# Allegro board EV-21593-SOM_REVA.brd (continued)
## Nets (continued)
PC_01/LP1_D2/TWI4_SDA/TRACE0_D05/SPI2_SEL4B: J2.92 U1.W15
PC_02/LP1_D3/TWI5_SCL/TRACE0_D06/SPI1_SEL6B: J2.90 U1.Y15
PC_03/LP1_D4/TWI5_SDA/TRACE0_D07/SPI2_SEL6B: J2.88 U1.W16
PC_04/LP1_D5/OSPI_SEL2B/SMC0_ADDR5: J2.86 U1.Y17
PC_05/LP1_D6/OSPI_SEL3B/TM0_TMR8/SMC0_ADDR6: J2.84 U1.V14
PC_06/LP1_D7/SPI1_RDY/SMC0_ADDR7: J2.82 U1.W17
PC_07/LP1_CLK/OSPI_SEL4B/TM0_TMR9/SYS_FAULT: J2.100 U1.Y18
PG1: R56.2 U14.2 U15.1
PG3: R62.1 U5.1 U14.11
PG4: R61.1 U5.14
RXD: U10.2 U11.8
SPIFLASH_SPI2D2: R79.2 U2.9 U7.4
SPIFLASH_SPI2D3: R78.2 U2.1 U8.4
SYS_BMODE0: R20.1 SW1.1 U1.B10
SYS_BMODE1: R21.1 SW1.2 U1.B9
SYS_BMODE2: R22.1 SW1.4 U1.A8
SYS_CLKIN0: R23.2 R33.2 U1.N1
SYS_CLKOUT: J3.38 U1.M3
SYS_XTAL0: R32.1 U1.L1
TWI2_SCL: J2.39 R68.2 R70.2 R112.2 U9.12 U16.8
TWI2_SDA: J2.41 R67.2 R69.2 R113.2 U9.19 U16.9
TXD: U10.30 U11.11
USB_SHELL: C192.1 P2.6 P2.7 P2.8 P2.9 R82.1
USB_VBUS: C191.1 D1.1 FER1.1 P2.1
VTT: C1.1 C2.1 C3.1 C4.1 C17.1 C18.1 C19.1 C20.1 C34.1 C35.1 C201.1 C202.1 C203.1 C204.1 C205.1 C206.1 C207.1 RN1.5 RN1.6 RN1.7 RN1.8 RN2.5 RN2.6 RN2.7 RN2.8 RN3.5 RN3.6 RN3.7 RN3.8 RN4.5 RN4.6 RN4.7 RN4.8 RN5.5 RN5.6 RN5.7 RN5.8 RN6.5 RN6.6 RN6.7 RN6.8 RN7.7 RN7.8 U12.3 U12.5
~CON_RESET_IN: J3.96 R51.2 U18.2
~CTS: R86.2 U10.8 U11.3
~DMC0_CAS: RN6.3 U1.E20 U13.K3
~DMC0_CK: R16.2 U1.J19 U13.K7
~DMC0_CS0: RN6.4 U1.F20 U13.L2
~DMC0_LDQS: U1.F1 U13.G3
~DMC0_RAS: RN6.1 U1.F19 U13.J3
~DMC0_RESET: R6.2 RN2.1 U1.B12 U13.T2
~DMC0_UDQS: U1.A4 U13.B7
~DMC0_WE: RN1.3 U1.A12 U13.L3
~JTG0_TRST: J3.56 P1.9 R92.2 R93.1 U1.A10
~RTS: R87.2 U10.32 U11.6
~SP2IFLASH_CS_EN: R75.2 R81.1 U6.1 U16.20
~SPI2D2_D3_EN: R74.1 R76.2 U7.1 U8.1 U16.21
~SPIFLASH_CS: R77.2 U2.7 U6.4
~SYS_FAULT: R9.2 R10.2 U1.A11
~SYS_HWRST: J3.94 R12.1 R46.2 R48.2 U1.A9 U2.3 U4.2 U16.14
~SYS_RESOUT: R11.2 U1.C10
~TARGET_RESET: J3.58 R50.2 R94.2 U18.1
~UART0_EN: R88.1 U11.10 U11.13 U16.22
~UART0_FLOW_EN: R89.1 U11.1 U11.4 U16.23
$3N3239: R2.2 U1.G20 U1.J4
$3N3333: R5.1 U13.L8
$3N3334: C11.2 C12.1 C13.1 C14.1 C15.1 C16.1 R3.2 R4.1 R7.1 U13.H1 U13.M8
$3N6009: C7.1 R100.2 R101.1 U12.1
$3N6012: R8.1 U12.6
$4N2087: LED1.K R9.1
$5N38: R71.1 R73.2 U2.16
$5N56: R72.1 R80.2 U2.8
$6N1711: C28.1 C29.1 FER3.3 U1.L20
$6N2071: R13.1 U1.L18
$6N3598: C30.1 C31.1 FER4.3 U1.L19
$6N4036: FER4.1 R14.2
$6N5154: C33.2 R15.1
$6N5877: R119.2 R120.2 U1.L7 U1.M7
$8N2576: C145.1 R25.2 U9.7 U9.24
$8N2596: R23.1 U9.22
$8N2617: R18.1 R19.2 U9.5
$8N2622: U9.1 Y2.2
$8N2623: U9.2 Y2.1
$8N2657: R24.1 U9.14
$8N3809: C144.1 R27.2 U9.16 U9.20
$8N3812: C143.1 R28.2 U9.11 U9.15
$8N3997: R30.1 U9.18
$8N3999: R31.1 U9.10
$8N4014: R32.2 R34.1 R35.1
$8N4015: C142.1 R33.1 R34.2 Y1.2
$8N4293: C141.1 R35.2 Y1.1
$9N2124: FER2.1 P2.5
$9N2147: LED7.K R83.1
$9N2148: LED8.K R84.1
$9N2149: R84.2 U10.22
$9N2150: R83.2 U10.21
$9N2153: D2.1 P2.2 U10.15
$9N2154: D2.2 P2.3 U10.14
$9N2155: C193.1 C194.1 FER1.2 U10.19
$9N2158: R85.2 U10.18
$9N3466: P1.10 R94.1
$10N4563: J3.95 R99.2
$10N4564: J3.93 R98.2
$10N4565: J3.91 R97.2
$10N4566: J3.89 R96.2
$10N4567: J3.87 R95.2
$11N466: R47.2 U4.3 U17.4
$11N467: LED6.K R46.1
$11N468: R49.2 SW2.2 U17.2
$11N469: U17.1 U18.4
$11N1122: LED4.K R38.1
$11N1123: LED5.K R37.1
$11N1124: LED3.K R39.1
$11N1132: LED2.K R36.1
$11N1711: LED2.A U16.19
$11N1713: LED5.A U16.18
$11N1715: LED4.A U16.17
$11N2516: R41.1 R42.2 U16.12
$11N2517: R44.1 R45.2 U16.13
$11N2518: R40.2 R43.1 U16.11
$12N6006: C163.2 R54.1 R55.2 U15.19 U15.20
$12N6225: L3.1 U14.5 U14.6
$12N6230: C151.2 R52.1 R63.2 U14.12
$12N7569: C162.2 L4.1 U15.8 U15.9 U15.10
$12N7589: C162.1 U15.7
$12N7788: R57.2 R58.2 R121.1 U15.15
$12N7803: C168.1 R121.2 R122.1 R123.1 R124.2 U15.18
$12N7837: R59.1 U15.17
$12N8016: C173.2 U5.16
$12N8049: C174.1 R60.2
$12N8051: C174.2 C185.2 R65.1 U5.17
$12N8198: L5.1 U5.6 U5.7 U5.8 U5.9
$12N8425: R66.2 R117.1
$12N8479: C178.2 C218.1 R64.2 R65.2 R66.1 R116.1 U5.18
$12N8484: R52.2 R118.1
$12N8942: R29.2 R127.2 U15.14
$13N133: C208.1 D4.A D5.K P3.A4 P3.A9 P3.B4 P3.B9 R110.1 U19.5 U19.6 U19.7 U19.8 U19.9
$13N256: R17.2 R103.1 U21.13
$13N259: R102.2 R104.1 U21.12
$13N306: R105.1 R115.1 U21.6
$13N308: R112.1 U21.7
$13N309: R113.1 U21.8
$13N457: R106.2 R107.1 R108.1 U19.4 U20.4
$13N525: C212.2 R108.2
$13N528: R107.2 U21.16
$13N538: R114.1 U21.19
$13N593: C213.1 D4.K R109.1 R110.2
$13N599: R109.2 U21.18
$13N626: R111.2 U21.9

Pads without a net: D1 3 4 6; D2 4 5 6 7 9 10; D3 4 5; J1 27 28 29 30 31 32 33 34 35 36 37 38 48 50 52 54 57 58 59 60 61 62 63 64 65 66 67 68 69 70 71 72 73 74 75 76 77 78 79 80 81 82 83 84 85 86 89 91 93 95 97 99; J2 29 53 54 55 56 57 58 59 60 61 63 64 65 66 67 69 70 72 73 74 75 77; J3 3 4 5 6 7 8 9 10 11 12 13 14 15 16 17 18 19 20 21 23 24 26 27 28 29 30 31 32 33 34 35 37 43 45 47 49 51 53 55 57 59 61 62 63 64 65 66 67 68 69 70 71 72 73 74 75 77 78 79 80 81 82 83 84 86 88; P1 7; P2 4 10 11; P3 A2 A3 A6 A7 A8 A10 A11 B2 B3 B6 B7 B8 B10 B11 S3 S4; RN7 3 4 5 6; SW1 8 C1; SW2 3 4 5; U2 4 5 6 11 12 13 14; U3 4; U9 8 9 13 17 21; U10 3 5 6 7 9 10 11 12 13 23 25 27 28 29 31; U12 9; U13 J1 J9 L1 L9; U15 5 12 16 22 23 24 25; U16 1 2 3 4 7 10 15 16 24 25 26 27 28; U21 11 14 15 17 20 V1 V2 V3 V4 V5; ZF1 1; ZF2 1; ZF3 1; ZF4 1; ZF5 1; ZF6 1

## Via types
v1: diameter 0.445, hole 0.152, TOP to BOTTOM, 2159 vias
v2: diameter 0.635, hole 0.305, TOP to BOTTOM, 1154 vias
v3: diameter 0.635, hole 0.302, TOP to BOTTOM, 121 vias

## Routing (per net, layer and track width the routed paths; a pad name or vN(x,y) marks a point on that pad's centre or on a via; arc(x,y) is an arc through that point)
1V2: length 2.1
  TOP w0.254: v2(46.35,96.65) 46.6,96.27 U21.21
  BOTTOM w0.508: C210.2 v2(46.35,96.65)
2V7: length 18.1
  TOP w0.254: v2(45.47,96.65) 45.6,96.27 U21.23
  TOP w0.305: R17.1 R102.1 v2(47.62,88.9)
  L5_SIG w0.305: v2(47.62,88.9) 47.62,89.66 47.12,90.17 45.59,90.17 45.02,90.74 43.37,90.74 42.8,91.31 42.8,96.14 43.31,96.65 v2(45.47,96.65)
  BOTTOM w0.508: C209.2 v2(45.47,96.65)
3V: length 108.9
  TOP w0.254: v2(52.44,72.19) 52.44,72.49 U12.7 ; v2(52.44,71.39) 52.44,70.99 U12.10
  TOP w0.305: R92.1 v2(10.79,47.62) ; U22.4 55.12,7.21 55.12,6.22 54.86,5.97 R125.1 ; U22.4 55.08,7.37 55.34,7.37 55.75,7.77 C219.1 56.64,7.77 ; U22.4 53.98,7.31 53.72,7.56 53.72,9.53 54.1,9.91 54.1,10.44 R126.1 54.2,11.18 53.69,11.68 53.69,12.45 54.2,12.95 54.2,20.47 v2(53.59,21.08) v2(53.59,21.84) ; TP3.1 v2(11.68,26.42) ; TP3.1 v2(11.68,28.19) ; TP3.1 v2(9.91,26.42) ; TP3.1 R53.2 ; TP3.1 v2(9.91,28.19) ; R45.1 12.32,71.25 v2(13.33,71.25) 14.22,71.25 R42.1 ; v2(5.71,80.9) SW1.C ; v2(18.92,63.37) 18.54,63.26 U16.5 ; U8.5 18.08,39.38 v2(18.1,39.37) ; v2(15.24,71.25) 16.13,71.25 R40.1 ; v1(58.8,28.07) 58.8,27.3 C149.1 58.93,27.3 59.56,26.67 59.56,25.71 U4.4 ; R47.1 R48.1 55.15,21.11 v1(55.12,21.08) ; v1(58.8,33.27) 58.8,32.38 C147.1 58.9,31.18 59.28,30.79 U17.5 ; v2(18.1,31.75) 18.08,31.76 U6.5 ; U11.14 17.27,79.04 v2(16.89,78.74) ; v1(20.62,66.34) R10.1 ; v2(22.23,37.46) 22.23,38.48 21.97,38.73 U2.2 ; R11.1 21.34,63.62 21.22,63.74 v1(20.62,63.74) ; v1(19.94,69.85) LED1.A ; v2(18.1,35.56) 18.08,35.57 U7.5 ; R49.1 54.23,29.84 v2(54.23,30.73) 54.23,31.75 LED6.A ; R50.1 v2(53.09,39.37) ; v1(59.05,42.16) 58.9,41.78 C148.1 59.44,40.74 59.44,39.68 U18.5 ; v2(6.35,99.57) LED7.A ; v2(4.45,99.57) LED8.A ; R51.1 v2(53.09,38.1) ; v2(8.26,58.42) LED3.A
  TOP w0.406: C8.1 v2(52.44,69.79)
  L2_PWR w0.406: 10.15,27.95 10.26,27.84 ; 10.15,26.66 10.26,26.77 ; 11.44,26.66 11.33,26.77 ; 11.44,27.95 11.33,27.84
  BOTTOM w0.254: C189.1 17.15,31.75 v2(18.1,31.75) ; v2(18.1,39.37) 17.15,39.37 C188.1 ; v2(18.1,35.56) 17.15,35.56 C187.1
  BOTTOM w0.305: 35.42,39.34 R67.1 ; 35.42,39.34 33.82,39.34 R68.1 ; 35.42,39.34 v1(36.22,39.34) ; R91.1 18.57,76.96 v2(20.19,76.96) ; v2(24.77,34.8) 23.59,34.8 R77.1 ; v2(10.79,33.66) R76.1 ; R87.1 v2(12.19,74.3) ; R19.1 43.18,32 v2(42.16,32) ; C186.1 v2(22.23,37.46) ; R90.1 v2(14.73,73.91) ; v2(18.92,63.37) C146.1 ; R25.1 v2(43.18,39.37) ; v2(26.03,33.02) R79.1 ; R75.1 v2(12.7,29.84) ; v2(16.89,78.74) 16,78.74 C190.1 ; R86.1 v2(12.19,79.88) ; v2(24.77,33.02) R80.1 ; R28.1 v2(48.89,31.12) ; R78.1 v2(23.49,37.46)
  BOTTOM w0.508: P1.1 3.81,56.9 4.32,57.4 7.87,57.4 8.26,57.79 v2(8.26,58.42) 8.26,60.07 7.62,60.71 v2(1.4,60.71)
  vias: v2(52.44,70.59) v2(52.44,70.59)
3V3OUT_FT232RQ: length 22.3
  TOP w0.254: U10.16 14.12,89.03 v2(13.08,89.03) ; U10.1 19.43,84.61 v2(19.81,84.33)
  TOP w0.762: v2(19.81,84.33) 20.57,84.33 20.83,84.58 20.83,90.3 20.45,90.68 13.46,90.68 13.08,90.3 v2(13.08,89.03)
  BOTTOM w0.305: v2(13.08,89.03) R85.1 ; v2(19.81,84.33) C195.1 C196.1
GND: length 516.4
  TOP w0.203: U1.L12 v1(33.82,53.34) ; U1.J13 v1(34.62,54.94) U1.H13 ; U1.D4 v1(27.42,58.94) ; U1.V16 v1(37.82,46.94) ; U13.J2 v1(33.02,73.54) ; U1.W1 v1(25.02,46.14) ; U1.T1 v1(25.02,48.54) ; U1.C5 v1(28.22,59.74) ; U1.J8 v1(31.42,54.94) ; U1.R17 v1(38.62,49.34) ; U1.V18 v1(39.42,46.94) ; U1.J9 v1(32.22,54.94) ; U1.D14 v1(36.22,58.94) ; U1.L2 v1(25.82,52.54) ; U1.Y20 v1(40.22,45.34) U1.Y19 ; U1.U17 v1(38.62,47.74) ; U1.M9 v1(32.22,52.54) ; U1.J3 v1(26.62,54.94) ; U1.Y5 v1(28.22,45.34) ; U1.K17 v1(38.62,54.14) ; U1.U5 v1(28.22,47.74) ; U1.V3 v1(26.62,46.94) ; U1.C3 v1(26.62,59.74) ; U1.H8 v1(31.42,55.74) ; U13.G1 v1(31.42,72.74) ; U1.L10 v1(32.22,53.34) ; U1.K19 v1(40.22,54.14) ; U1.K9 v1(31.42,54.14) U1.K8 ; U1.N13 v1(34.62,51.74) U1.M12 ; U1.D18 v1(39.42,58.94) ; U13.J8 v1(33.02,79.14) ; U1.D16 v1(37.82,58.94) U1.D17 ; U1.M8 v1(31.42,52.54) ; U1.U16 v1(37.82,47.74) ; U1.K20 v1(41.02,54.14) ; U1.H11 v1(33.02,54.94) U1.H10 ; U1.L9 v1(31.42,53.34) U1.L8 ; U1.J12 v1(33.82,54.94) U1.H12 ; U1.W2 v1(25.82,46.14) ; U1.A20 v1(41.02,61.34) ; U1.Y2 v1(25.82,45.34) ; U1.L3 v1(26.62,52.54) ; U13.B3 v1(27.42,74.34) ; U1.M10 v1(33.02,52.54) ; U1.B19 v1(40.22,60.54) ; U1.C6 v1(29.02,59.74) ; U13.B1 v1(27.42,72.74) ; U1.M11 v1(33.02,51.74) U1.N11 ; U1.G3 v1(26.62,56.54) ; U1.C17 v1(38.62,59.74) ; U1.D7 v1(29.82,58.94) ; U13.T9 v1(38.62,79.94) ; U13.M1 v1(35.42,72.74) ; U13.F9 v1(30.62,79.94) ; U1.M1 v1(25.82,51.74) U1.M2 ; U1.N17 v1(38.62,51.74) U1.M17 ; U1.J18 v1(39.42,54.94) ; U1.V4 v1(27.42,46.94) ; U1.K11 v1(33.82,54.14) ; U13.G9 v1(31.42,79.94) ; U13.M9 v1(35.42,79.94) ; U1.D15 v1(37.02,58.94) ; U1.K1 v1(25.82,54.14) U1.K2 ; U1.D2 v1(25.82,58.94) ; U1.C4 v1(27.42,59.74) ; U1.R2 v1(25.82,49.34) ; U1.N18 v1(39.42,51.74) U1.M18 ; U1.P1 v1(25.02,50.14) ; U1.D5 v1(28.22,58.94) ; U1.N12 v1(33.82,51.74) ; U1.N9 v1(31.42,51.74) ; U1.F3 v1(26.62,57.34) ; U1.K13 v1(34.62,54.14) U1.K12 ; U1.D13 v1(35.42,58.94) ; U1.L17 v1(38.62,52.54) ; U1.H9 v1(32.22,55.74) ; U1.E3 v1(26.62,58.14) ; U13.B9 v1(27.42,79.94) ; U13.D8 v1(29.02,79.14) ; U1.C14 v1(36.22,59.74) ; U13.D1 v1(29.02,72.74) ; U1.P20 v1(41.02,50.14) ; U1.Y13 v1(35.42,45.34) ; U1.K18 v1(39.42,54.14) ; U1.K3 v1(26.62,54.14) ; v1(38.62,50.14) U1.P17 ; U13.E2 v1(29.82,73.54) ; U1.H2 v1(25.82,55.74) ; v1(40.22,50.14) U1.P19 ; U1.T4 v1(28.22,48.54) ; U1.N10 v1(32.22,51.74) ; U1.Y16 v1(37.82,45.34) ; U1.H18 v1(39.42,55.74) U1.G18 ; U13.E1 v1(29.82,72.74) ; U1.C15 v1(37.02,59.74) ; U13.P9 v1(37.02,79.94) ; U1.L11 v1(33.82,52.54) ; U13.T1 v1(38.62,72.74) ; U1.C16 v1(37.82,59.74) ; U1.U1 v1(25.02,47.74) ; U13.G8 v1(31.42,79.14) ; U1.Y1 v1(25.02,45.34) ; U1.U4 v1(27.42,47.74) ; U1.N2 v1(25.82,50.94) ; U1.V15 v1(37.02,46.94) ; U1.C18 v1(39.42,59.74) ; U1.B1 v1(25.02,60.54) ; U1.A1 v1(25.02,61.34) ; U1.J10 v1(32.22,54.14) ; U1.B2 v1(25.82,60.54) ; U1.F18 v1(39.42,56.54) ; U1.D6 v1(29.02,58.94) ; U1.H3 v1(26.62,55.74) ; U1.W20 v1(40.22,46.14) U1.W19 ; U13.A9 v1(26.62,79.94) ; U1.N8 v1(30.62,51.74) ; U13.P1 v1(37.02,72.74) ; U1.D12 v1(34.62,58.94) ; U1.J11 v1(33.02,54.14) ; U1.M13 v1(35.42,52.54) ; U1.K10 v1(33.02,53.34) ; U1.Y7 v1(29.82,45.34) ; U1.L13 v1(34.62,52.54) ; U1.E18 v1(39.42,58.14) ; U1.T17 v1(38.62,48.54) ; v1(37.82,52.54) U1.L16 ; U13.E8 v1(29.82,79.14)
  TOP w0.254: U10.20 14.36,86.61 v3(14.6,86.36) ; v3(17.15,86.36) 17.02,86.23 17.02,86.11 U10.4 ; v3(55.44,72.79) 55.44,72.69 55.3,72.54 ; U10.24 12.83,84.61 v2(12.19,84.96) ; v2(48.01,13.33) 46.1,13.33 46.1,14.17 U14.1 ; U9.23 44.33,34.54 v3(44.2,34.54) ; 55.3,72.49 U12.4 ; 55.3,72.49 55.24,72.49 55.3,72.54 ; 55.3,72.49 55.3,72.54 ; 55.3,72.49 55.3,72.19 55.24,72.19 v3(55.04,71.99) 54.79,71.99 ; 54.79,71.99 U12.8 ; 54.79,71.99 U12.11 ; U21.22 46.11,95 v3(46.35,95) ; U9.6 43.56,32.41 v3(44.2,32.77) ; U10.17 12.22,88.11 v2(12.19,88.14) ; v2(33.66,18.16) 33.66,17.64 U5.5 ; U5.2 34.16,16.14 34.8,15.62 ; v3(15.88,85.09) 15.75,85.22 14.63,85.22 U10.26 ; U14.7 44.19,15.82 C157.2 ; U9.3 44.2,33.9 v3(44.2,33.66) 44.2,33.49 44.11,33.41 U9.4 ; C158.2 20.95,15.49 U15.4 17.66,15.49 U15.13 14.7,15.49 C160.2 ; U21.3 45.34,94.23 v3(45.34,93.98) ; U5.10 30.61,17.64 v2(30.61,18.16) ; v3(46.35,92.96) 46.6,92.96 U21.10
  TOP w0.305: P3.A1 33.48,94.23 34.56,94.23 P3.S1 34.79,94.48 34.79,94.87 34.29,95.37 P3.B12 ; v2(36.32,19.69) 36.32,20.68 C171.1 37.34,20.68 v2(37.34,19.69) ; C164.2 23.75,20.83 v2(24.77,20.83) ; C164.2 v2(24.77,21.72) ; C164.2 23.75,22.61 v2(24.77,22.61) ; v1(48.62,62.94) C100.2 ; v1(48.62,61.34) C108.2 ; v2(24.77,27.43) 23.75,27.43 C166.2 ; v2(41.78,88.9) R105.2 ; C217.1 v2(37.21,14.35) R117.2 ; P3.B1 26.67,95.37 26.17,94.87 26.17,94.48 P3.S2 26.4,94.23 27.48,94.23 P3.A12 ; v1(45.42,62.94) C96.2 ; C161.2 11.81,15.39 ; C214.2 C215.2 C216.2 51.67,19.81 v2(50.55,19.81) ; v1(43.42,40.94) 43.42,41.66 ; U5.19 v3(31.62,17.15) ; v2(14.22,67.06) R41.2 ; U6.3 14.48,30.47 v2(13.97,29.84) ; v2(34.92,19.69) C170.1 ; U18.3 58.04,37.79 v1(58.55,37.46) ; v1(20.62,55.34) C52.2 ; C101.2 v1(33.82,65.54) ; v1(20.62,50.54) C70.2 ; C165.2 23.75,25.91 v2(24.77,25.91) ; C165.2 v2(24.77,25.02) ; C165.2 23.75,24.13 v2(24.77,24.13) ; C93.2 v1(45.42,61.34) ; U4.1 57.28,25.52 57.28,26.64 C149.2 58.04,27.3 v1(58.04,28.07) ; v1(48.62,51.74) C49.2 ; v1(58.04,34.29) 56.37,34.29 SW2.1 ; 35.42,41.66 v1(35.42,40.94) ; v1(45.42,58.14) C104.2 ; 21.34,45.34 20.7,45.34 v1(20.7,45.34) ; C166.2 v2(24.77,28.32) ; C166.2 23.75,29.21 v2(24.77,29.21) ; v1(30.62,40.94) 30.62,41.66 ; D1.5 v2(17.78,92.71) D1.2 ; v2(48.01,13.33) R118.2 48.89,12.55 48.89,10.39 C176.2 ; v1(48.62,50.14) C47.2 ; C153.2 49.91,17.76 49.91,16.26 48.26,16.26 C156.2 ; v1(32.22,65.54) C98.2 ; C62.2 v1(20.62,56.74) ; v1(42.02,40.94) C126.2 ; v1(45.42,59.74) C94.2 ; v2(33.15,29.97) C177.2 ; v2(25.91,88.9) D5.A ; D3.3 29.97,90.79 v2(29.46,90.55) ; v2(4.45,64.77) R37.2 ; v2(10.54,25.15) 10.54,24.23 C155.2 ; R60.1 C185.1 C173.1 ; v1(48.62,46.94) C48.2 ; v2(11.43,9.65) R123.2 ; R44.2 11.43,67.85 v2(11.43,67.82) ; v1(20.62,52.94) C54.2 ; v2(2.54,64.77) R36.2 ; v2(56.52,9.53) C219.2 55.75,8.74 55.34,9.14 55.08,9.14 U22.5 ; v3(17.27,16.26) 17.65,15.49 U15.21 ; v2(21.34,10.29) 22.23,10.29 C167.1 21.98,10.31 R54.2 ; v2(29.34,19.94) C169.2 ; C175.2 40.77,16.99 40.77,15.82 C157.2 ; v1(57.91,42.16) 57.91,41.3 C148.2 ; U17.3 57.12,28.96 v1(58.04,28.96) ; v1(25.82,40.94) 25.82,41.66 ; U8.3 14.6,38.09 14.6,37.59 14.35,37.34 v2(13.33,37.34) ; v1(45.02,40.94) 45.02,41.66 ; U22.2 v2(51.31,8.26) ; v2(8.26,56.52) C141.2 ; v1(58.04,33.27) 58.04,32.38 C147.2 ; v2(52.07,93.22) D6.A ; R38.2 v2(6.35,64.77) ; v2(11.43,25.15) C155.2 ; C155.2 12.32,24.23 v2(12.32,25.15) ; v2(16.26,67.06) 16.26,67.85 R43.2 ; v2(8.26,64.77) R39.2 ; C57.2 v1(20.62,58.14) ; v1(20.62,54.14) C53.2 ; v2(31.12,31.75) 30.52,32.35 29.32,32.35 U2.10 ; v2(13.97,12.19) R57.1 ; v2(18.92,64.26) 18.41,63.91 U16.6 ; v2(15.24,9.65) R59.2 ; v2(36.32,90.04) 36.32,91.18 C213.2 37.34,91.18 v2(37.34,90.04) ; v1(45.42,45.34) C46.2 ; v1(33.82,40.94) C88.2 ; v1(35.42,65.54) C103.2 ; C105.2 v1(37.02,65.54) ; v2(13.33,33.66) 13.96,34.28 U7.3 ; C63.2 v1(20.62,61.34) ; D2.3 D2.8 v2(13.97,92.08) ; v2(8.13,45.47) 8.51,45.09 C142.2 ; v1(38.62,65.54) C106.2 ; v2(16.51,9.65) C168.2 ; v2(12.7,9.65) R122.2 ; v2(10.79,46.35) R93.2 ; U11.7 11.43,75.14 v2(11.05,74.93) ; v2(27.94,19.94) 27.94,20.93 C172.2 26.92,20.93 v2(26.92,19.94) ; v2(60.32,66.04) 60.32,64.77 C154.2 61.59,65.41 v2(61.59,66.04) ; v1(20.62,65.15) 20.62,64.74 20.82,64.54 R12.2 ; v1(45.42,50.14) C38.2 ; v3(46.35,95) U21.25 ; 44.7,48.54 v1(45.42,48.54) ; v1(32.22,40.94) C83.2 ; v1(21.02,40.94) 21.02,41.66 ; v1(20.62,49.14) C55.2 ; v1(20.7,46.61) C36.2 ; v2(24.13,90.93) 25.17,90.93 C208.2 25.17,91.95 v2(24.13,91.95) ; v1(48.62,48.54) C37.2
  TOP w0.356: C15.2 42.02,71.34 v1(42.02,72.14) 42.02,72.94 C16.2 ; C13.2 42.02,76.14 v1(42.02,75.34) 42.02,74.54 C14.2 ; C12.2 42.02,77.74 v1(42.02,78.54) 42.02,79.34 R4.2
  TOP w0.406: v1(32.22,83.14) 32.22,82.42 ; v1(37.82,69.54) 37.82,70.26 ; v1(30.62,69.54) 30.62,70.26 ; v1(28.22,83.14) 28.22,82.42 ; 29.82,82.42 v1(29.82,83.14) ; U3.2 54.74,58.93 54.36,58.55 54.36,58.33 53.96,58.33 C150.2 53.85,58.29 v2(52.58,58.29) ; v2(61.59,68.83) 60.54,68.83 60.54,69.6 ; v2(53.98,67.18) R101.2 ; 60.54,75.44 v2(60.96,75.44) v2(61.72,75.44) ; 60.54,76.2 v2(60.96,76.2) v2(61.72,76.2) ; v2(52.44,66.19) C8.2 ; 60.54,69.6 C6.2 ; 60.54,69.6 v2(61.59,69.6) ; v2(61.72,76.96) v2(60.96,76.96) 60.54,76.96 ; 26.74,95.55 26.56,95.36 ; v2(55.24,67.18) C7.2 ; v2(61.59,68.07) 60.54,68.07 C5.2 60.54,67.31 v2(61.59,67.31) ; 28.22,70.26 v1(28.22,69.54) ; v2(61.72,74.68) v2(60.96,74.68) 60.54,74.68 60.56,73.91 C4.2 ; 37.82,82.42 v1(37.82,83.14) ; v1(34.62,83.14) R5.2
  TOP w1.016: 11.81,15.39 C160.2 ; C158.2 C159.2
  L3_GND w0.406: 26.66,93.47 26.56,93.58 ; 35.3,93.47 35.2,93.58 ; 25.66,95.47 25.76,95.36 ; 35.3,95.47 35.2,95.36 ; 25.66,93.47 25.76,93.58 ; 34.3,95.47 34.4,95.36 ; 34.3,93.47 34.4,93.58 ; 26.66,95.47 26.56,95.36
  L6_GND w0.406: 25.66,95.47 25.76,95.36 ; 34.3,95.47 34.4,95.36 ; 26.66,95.47 26.56,95.36 ; 26.66,93.47 26.56,93.58 ; 35.3,93.47 35.2,93.58 ; 35.3,95.47 35.2,95.36 ; 34.3,93.47 34.4,93.58 ; 25.66,93.47 25.76,93.58
  BOTTOM w0.14: C152.2 27.3,26.17 27.3,26.29 28,26.99 28,27.56 28.51,28.07 31.5,28.07 31.88,28.45 31.88,36.07 32.77,36.96 32.77,43.81 33.02,44.07 v1(33.02,51.74)
  BOTTOM w0.254: C189.2 17.15,30.48 v2(18.1,30.48) ; v2(18.1,34.29) 17.15,34.29 C187.2 ; v2(18.1,38.1) 17.15,38.1 C188.2
  BOTTOM w0.305: v1(16.13,1.65) 15.92,2.16 J2.1 ; 21.36,45.34 v1(20.7,45.34) ; 43.69,81.92 42.93,81.92 v2(42.29,82.55) ; 43.69,81.92 C1.2 ; 43.69,81.92 v1(43.69,82.3) ; v1(23.02,65.15) 22.51,64.64 21.82,64.64 ; v1(35.18,84.96) C34.2 ; v1(34.62,51.74) C130.2 ; v1(20.62,47.94) C67.2 ; C78.2 v1(42.02,40.94) ; v1(23.75,1.65) 23.54,2.16 J2.25 ; v1(45.59,63.88) 45.59,64.29 45.34,64.54 C90.2 ; v3(44.2,34.54) 43.18,34.54 C145.2 43.18,34.44 ; J3.39 2.03,31.88 v1(1.52,32) ; v2(16,80.52) C190.2 ; v2(41.27,31.12) R18.2 ; 25.82,41.66 v1(25.82,40.94) ; v1(48.42,40.94) 47.22,40.94 ; 47.22,40.94 v1(46.02,40.94) ; 47.22,40.94 C39.2 ; 21.82,64.64 21.13,64.64 v1(20.62,65.15) ; 21.82,64.64 C111.2 ; 19.05,46.61 18.62,46.61 C43.2 ; 19.05,46.61 19.05,47.24 v1(19.81,47.24) ; 19.05,46.61 v1(19.81,46.61) ; v1(26.62,55.74) 27.34,55.74 ; v1(31.42,53.34) 31.12,53.64 C32.2 ; v1(15.88,50.55) 16.92,50.55 C42.2 ; J3.46 8.13,29.97 v1(8.51,30.23) ; v1(5.46,33.4) 5.71,33.15 J3.36 ; v2(16,73.91) R88.2 ; v1(41.91,64.77) C205.2 ; v1(22.62,40.94) 22.62,41.66 ; J2.48 30.53,5.71 v1(30.42,5.33) ; v2(32.13,87.63) 32.26,87.76 C206.2 ; v1(5.46,37.59) J3.22 ; J1.94 57.66,42.04 v1(57.91,42.16) ; v1(49.22,46.14) 50.42,46.14 ; 50.42,46.14 C44.2 ; 50.42,46.14 v1(51.62,46.14) ; 44.7,45.34 v1(45.42,45.34) ; v1(26.62,52.54) 26.62,52.99 C61.2 ; v1(43.69,72.01) C201.2 ; 18.62,40.94 v1(19.82,40.94) ; 18.62,40.94 v1(17.42,40.94) ; 18.62,40.94 C40.2 ; 21.02,41.66 v1(21.02,40.94) ; v3(14.6,87.63) C193.2 ; J2.2 15.92,7.62 v1(15.62,8.13) ; J2.71 38.15,2.03 v1(38.1,1.65) ; v2(19.81,81.66) C195.2 ; J1.56 55.37,29.97 55.12,29.72 v1(55.12,28.96) ; C194.2 9.65,87.12 v2(9.65,88.14) ; v1(33.82,51.74) C120.2 ; 27.42,41.66 v1(27.42,40.94) ; v2(22.23,40) C186.2 ; v1(42.55,64.77) C35.2 ; C143.2 47.5,31.5 v2(48.01,31.5) ; J1.2 57.66,12.83 v1(58.04,13.21) ; v1(20.62,61.34) C63.2 ; v1(30.62,51.74) C131.2 ; C108.2 v1(48.62,61.34) ; v1(39.42,51.74) 39.42,50.94 C79.2 ; C210.1 46.74,99.32 v2(46.74,100.71) ; J2.68 36.88,5.71 v1(36.96,5.33) ; 45.02,41.66 v1(45.02,40.94) ; v1(61.85,26.29) 61.34,26.16 J1.43 ; v1(39.42,58.94) 39.07,58.79 C60.2 ; v2(48.89,88.9) R103.2 R104.2 ; v1(20.62,55.34) C52.2 ; C37.2 v1(48.62,48.54) ; v2(41.27,82.55) 41.27,83.59 C19.2 40.26,83.59 v2(40.26,82.55) ; C207.2 32.26,86.74 v2(32.13,86.61) ; v2(27.3,37.46) R71.2 ; v1(15.88,52.96) 15.88,52.94 C41.2 ; 28.5,49.44 C72.2 28.42,49.44 28.42,48.94 v1(28.22,48.54) ; v1(20.62,52.94) C54.2 ; v1(40.64,5.33) 40.69,5.71 J2.80 ; J2.79 40.69,4.06 v1(40.64,4.45) ; v1(45.42,61.34) C117.2 ; v1(1.52,43.94) J3.1 ; C106.2 v1(38.62,65.54) ; J1.46 55.63,26.8 v1(55.12,26.54) 55.5,26.15 55.5,26.16 55.75,26.16 J1.44 ; v1(61.85,39.88) 61.34,40.13 J1.87 ; v1(38.8,85.03) C204.2 ; v2(1.27,69.85) R21.2 ; 30.62,41.66 v1(30.62,40.94) ; C98.2 v1(32.22,65.54) ; J2.62 34.97,5.71 v1(34.8,5.33) ; C146.2 17.72,64.26 v2(18.92,64.26) ; v1(58.8,26.54) 59.18,26.8 J1.45 ; C38.2 v1(45.42,50.14) ; v1(0.89,17.53) 1.4,17.27 J3.85 ; v1(34.62,54.94) 35.42,54.94 C91.2 ; v1(31.42,51.74) C121.2 ; v1(45.42,54.94) R1.2 ; v2(2.16,80.9) 2.41,80.39 2.41,79.73 R22.2 ; v1(33.82,65.54) C101.2 ; J3.60 5.71,25.53 v1(5.46,25.4) ; v2(14.73,80.52) R89.2 ; J1.55 61.34,29.97 v1(61.85,30.48) ; 47.9,51.74 v1(48.62,51.74) ; v2(13.97,29.84) R81.2 ; v2(7.62,93.98) R82.2 ; 47.9,46.94 v1(48.62,46.94) ; J2.24 22.91,5.71 v1(23.11,5.33) ; v2(12.06,33.66) R74.2 ; v3(45.97,34.54) 45.97,35.18 46.2,35.41 46.99,35.41 ; v2(19.62,59.54) R15.2 ; C152.2 27.29,24.77 27.04,24.51 26.06,24.51 C179.2 ; v1(45.42,62.94) C118.2 ; 44.7,46.94 v1(45.42,46.94) ; v1(20.62,58.14) C57.2 ; v1(37.02,65.54) C119.2 ; v2(10.29,90.17) 10.29,91.21 FER2.2 11.3,91.21 v2(11.3,90.17) ; R20.2 9.4,79.72 9.4,80.39 v2(9.65,80.9) ; v1(20.62,51.74) C115.2 ; 33.82,41.66 v1(33.82,40.94) ; v1(31.42,52.54) C122.2 ; J3.76 5.59,20.45 5.21,20.83 v2(5.21,23.88) ; v1(1.52,31.12) 2.03,31.24 J3.41 ; C92.2 30.67,54.94 v1(31.42,54.94) ; v1(20.62,59.74) C66.2 ; v1(43.69,78.49) C202.2 ; v1(1.52,36.32) J3.25 ; C59.2 34.62,53.69 v1(34.62,54.14) ; 47.9,45.34 v1(48.62,45.34) ; 32.22,41.66 v1(32.22,40.94) ; v1(32.22,51.74) C123.2 ; v1(20.62,54.14) C53.2 ; J3.100 8.26,12.83 v1(8.76,12.57) ; v2(44.07,100.71) 44.07,99.32 C209.1 45.09,99.32 v2(45.09,100.71) ; v2(20.7,93.34) 20.32,92.96 19.69,92.96 C191.2 ; v2(18.54,81.66) C196.2 ; v1(20.62,50.54) C70.2 ; J1.1 59.31,12.83 v1(58.93,13.21) ; J2.51 31.8,2.03 v1(31.88,1.65) ; 24.22,41.66 v1(24.22,40.94) ; v1(4.7,15.62) 5.08,16 J3.90 ; v2(42.55,100.71) 42.55,99.32 C211.1 41.53,99.32 v2(41.53,100.71) ; R127.1 v2(13.97,12.19) ; C104.2 v1(45.42,58.14) ; v2(7.62,99.82) C192.2 ; v1(32.22,55.74) C97.2 ; C103.2 v1(35.42,65.54) ; v1(35.42,40.94) 35.42,41.66 ; 47.9,50.14 v1(48.62,50.14) ; C100.2 v1(48.62,62.94) ; C36.2 v1(20.7,46.61) ; v1(20.62,49.14) C55.2 ; v1(45.42,48.54) 44.7,48.54 ; v1(43.69,75.31) C203.2 ; 43.42,41.66 v1(43.42,40.94) ; v1(8.76,13.46) J3.98 ; C94.2 v1(45.42,59.74) ; v1(20.62,56.74) C62.2 ; v2(5.33,43.94) J3.2
  BOTTOM w0.406: 38.7,53.34 C56.2 38.62,53.34 v1(38.62,52.54) ; C10.2 v1(48.62,56.54)
  vias: v1(9.27,34.67) v1(16,5.33) v1(16,5.33) v1(16.38,47.37) v1(16.38,47.37) v1(19.69,62.74) v1(19.69,62.74) v1(19.69,62.74) v1(19.81,66.29) v1(19.81,65.15) v1(19.81,65.15) v1(19.81,65.15) v1(19.81,65.15) v1(21.34,8.13) v1(21.72,1.65) v1(24.51,1.65) v1(24.64,4.45) v1(24.77,5.33) v1(27.05,1.65) v1(31.24,4.45) v1(31.24,4.45) v1(35.94,4.45) v1(35.94,4.45) v1(35.94,4.45) v1(35.94,4.45) v1(35.94,4.45) v1(36.32,1.65) v1(36.32,1.65) v1(36.32,1.65) v1(36.32,1.65) v1(36.32,1.65) v1(40.26,1.65) v1(40.26,1.65) v1(40.26,1.65) v1(40.26,1.65) v1(40.26,1.65) v1(40.26,1.65) v1(40.26,1.65) v1(40.26,1.65) v1(44.07,1.65) v1(44.07,1.65) v1(44.07,1.65) v1(44.07,1.65) v1(44.07,1.65) v1(44.07,1.65) v1(44.07,1.65) v1(44.07,1.65) v1(45.09,14.99) v1(45.09,14.99) v1(45.09,14.99) v1(51.18,54.1) v1(55.12,45.72) v1(55.12,45.72) v1(55.12,45.72) v1(55.12,45.72) v1(55.12,45.72) v1(55.12,45.72) v1(55.12,45.72) v1(55.12,16.38) v1(55.12,16.38) v1(58.55,38.35) v1(58.55,38.35) v1(58.55,38.35) v1(58.8,34.29) v1(58.8,34.29) v1(58.93,19.43) v1(58.93,19.43) v1(58.93,19.43) v1(58.93,15.11) v1(58.93,15.11) v1(58.93,15.11) v1(61.85,17.91) v1(61.85,17.91) v1(61.85,17.91) v1(61.98,42.93) v1(61.98,42.93) v1(61.98,42.93) v1(61.98,42.93) v1(61.98,42.93) v1(61.98,42.93) v1(61.98,41.02) v1(61.98,41.02) v1(61.98,41.02) v1(61.98,41.02) v1(61.98,41.02) v1(61.98,41.02) v2(1.4,92.96) v2(1.4,62.23) v2(1.4,62.23) v2(1.4,58.42) v2(1.4,42.8) v2(1.4,39.37) v2(1.4,34.8) v2(1.4,34.8) v2(1.4,29.34) v2(1.4,29.34) v2(1.4,29.34) v2(1.4,29.34) v2(1.4,26.67) v2(1.4,26.67) v2(1.4,26.67) v2(1.4,26.67) v2(1.4,23.88) v2(1.4,23.88) v2(1.4,23.88) v2(1.4,23.88) v2(1.4,23.88) v2(1.4,21.46) v2(1.4,19.18) v2(1.52,78.49) v2(1.52,74.8) v2(1.52,74.8) v2(1.52,74.8) v2(1.52,74.8) v2(1.52,71.5) v2(1.52,71.5) v2(1.52,71.5) v2(1.52,71.5) v2(1.52,67.95) v2(1.52,67.95) v2(1.52,67.95) v2(1.52,67.95) v2(1.52,67.95) v2(2.67,76.84) v2(4.57,73.79) v2(4.57,73.79) v2(4.57,73.79) v2(4.83,26.16) v2(4.83,26.16) v2(4.83,26.16) v2(4.83,26.16) v2(4.83,26.16) v2(4.83,26.16) v2(4.83,26.16) v2(5.46,29.72) v2(5.46,29.72) v2(5.46,29.72) v2(5.46,29.72) v2(5.46,29.72) v2(5.46,29.72) v2(5.46,29.72) v2(5.46,29.72) v2(6.73,76.84) v2(6.73,76.84) v2(6.73,76.84) v2(6.73,74.55) v2(6.73,74.55) v2(6.73,74.55) v2(6.73,74.55) v2(6.73,71.25) v2(8.26,1.91) v2(8.38,8.38) v2(8.51,32.77) v2(8.51,32.77) v2(9.02,11.68) v2(9.02,11.68) v2(9.02,11.68) v2(9.91,77.6) v2(9.91,77.6) v2(9.91,77.6) v2(10.16,67.82) v2(10.16,67.82) v2(10.16,67.82) v2(10.16,67.82) v2(10.16,67.82) v2(10.16,67.82) v2(10.16,67.82) v2(10.16,67.82) v2(10.16,67.82) v2(10.79,55.63) v2(10.79,52.96) v2(10.79,52.96) v2(10.79,49.91) v2(10.79,49.91) v2(11.43,32.77) v2(11.43,5.84) v2(12.06,39.37) v2(12.06,37.34) v2(12.06,37.34) v2(12.19,82.68) v2(12.7,91.44) v2(12.7,1.91) v2(12.7,1.91) v2(14.48,4.45) v2(14.73,8.13) v2(14.86,82.68) v2(14.86,82.68) v2(14.86,82.68) v2(14.86,82.68) v2(15.88,40.26) v2(15.88,32.38) v2(15.88,32.38) v2(15.88,32.38) v2(19.05,89.54) v2(19.05,89.54) v2(19.81,86.74) v2(19.81,86.74) v2(22.23,34.67) v2(22.99,73.66) v2(23.49,63.63) v2(23.49,63.63) v2(24.13,50.93) v2(26.03,34.8) v2(26.03,34.8) v2(30.61,87.63) v2(30.61,87.63) v2(30.61,87.63) v2(30.61,87.63) v2(30.61,87.63) v2(30.61,87.63) v2(30.61,87.63) v2(30.61,87.63) v2(30.61,87.63) v2(30.61,86.61) v2(30.61,86.61) v2(30.61,86.61) v2(30.61,86.61) v2(30.61,86.61) v2(30.61,86.61) v2(30.61,86.61) v2(30.61,86.61) v2(30.99,36.58) v2(30.99,36.58) v2(30.99,34.16) v2(30.99,34.16) v2(31.12,83.82) v2(31.12,83.82) v2(31.12,83.82) v2(31.12,83.82) v2(31.12,83.82) v2(31.12,83.82) v2(31.12,83.82) v2(31.24,39.62) v2(31.24,39.62) v2(31.37,87.63) v2(31.37,86.61) v2(31.37,86.61) v2(31.37,86.61) v2(31.37,86.61) v2(31.37,86.61) v2(31.37,86.61) v2(31.37,86.61) v2(31.37,86.61) v2(33.4,33.15) v2(35.69,31.24) v2(35.94,36.2) v2(39.5,19.69) v2(39.5,19.69) v2(39.5,19.69) v2(39.5,18.92) v2(39.5,18.92) v2(39.5,18.92) v2(39.5,18.16) v2(39.5,18.16) v2(39.5,18.16) v2(40.51,19.69) v2(40.51,18.92) v2(40.51,18.92) v2(40.51,18.16) v2(40.51,18.16) v2(40.51,18.16) v2(40.51,18.16) v2(41.27,35.56) v2(41.27,33.78) v2(41.27,33.78) v2(41.53,19.69) v2(41.53,18.92) v2(41.53,18.92) v2(41.53,18.16) v2(41.53,18.16) v2(41.53,18.16) v2(42.29,60.71) v2(42.8,58.93) v2(42.93,55.75) v2(45.72,39.37) v2(47.88,36.83) v2(47.88,36.83) v2(47.88,36.83) v2(47.88,36.83) v2(47.88,36.83) v2(47.88,36.83) v2(48.26,4.57) v2(48.26,4.57) v2(48.26,4.57) v2(48.26,4.57) v2(48.26,4.57) v2(48.26,4.57) v2(48.26,4.57) v2(48.26,4.57) v2(48.26,1.91) v2(48.26,1.91) v2(48.26,1.91) v2(48.26,1.91) v2(48.26,1.91) v2(48.26,1.91) v2(48.26,1.91) v2(48.26,1.91) v2(48.51,19.81) v2(48.51,19.05) v2(48.51,19.05) v2(48.51,18.29) v2(48.51,18.29) v2(48.64,55.37) v2(48.64,55.37) v2(48.64,55.37) v2(48.64,55.37) v2(48.64,55.37) v2(49.53,19.81) v2(49.53,19.05) v2(49.53,19.05) v2(49.53,18.29) v2(49.53,18.29) v2(49.53,18.29) v2(50.16,63.25) v2(50.16,63.25) v2(50.55,19.05) v2(50.55,18.29) v2(50.55,18.29) v2(50.55,18.29) v2(51.18,63.25) v2(51.18,4.57) v2(51.18,4.57) v2(51.18,4.57) v2(51.18,4.57) v2(51.18,4.57) v2(51.18,4.57) v2(51.18,4.57) v2(51.18,4.57) v2(51.18,4.57) v2(51.18,1.78) v2(51.18,1.78) v2(51.43,43.94) v2(52.7,87.5) v2(52.7,87.5) v2(52.7,86.23) v2(52.7,86.23) v2(52.7,84.96) v2(52.7,84.96) v2(52.7,83.69) v2(53.09,46.99) v2(53.09,46.99) v2(53.09,46.99) v2(53.09,46.99) v2(53.09,46.99) v2(53.09,46.99) v2(53.09,46.99) v2(53.98,87.5) v2(53.98,87.5) v2(53.98,86.23) v2(53.98,86.23) v2(53.98,84.96) v2(53.98,84.96) v2(53.98,83.69) v2(53.98,83.69) v2(54.61,12.06) v2(54.61,12.06) v2(55.12,50.29) v2(55.24,87.5) v2(55.24,86.23) v2(55.24,84.96) v2(55.24,83.69) v2(55.24,1.91) v2(57.66,8.26) v2(59.05,9.78) v2(59.05,9.78) v2(59.56,45.21) v2(59.56,45.21) v2(59.56,45.21) v2(59.56,45.21) v2(59.56,45.21) v2(59.56,45.21) v2(60.2,77.72) v2(60.2,77.72) v2(60.2,76.96) v2(60.2,76.96) v2(60.2,76.96) v2(60.2,76.2) v2(60.2,76.2) v2(60.2,76.2) v2(60.2,75.44) v2(60.2,75.44) v2(60.2,75.44) v2(60.2,74.68) v2(60.2,74.68) v2(60.2,73.91) v2(60.2,73.91) v2(60.2,73.91) v2(60.32,80.39) v2(60.32,80.39) v2(60.32,79.12) v2(60.32,79.12) v2(60.32,79.12) v2(60.58,11.3) v2(60.64,8.26) v2(60.96,77.72) v2(60.96,77.72) v2(60.96,73.91) v2(60.96,73.91) v2(61.59,80.39) v2(61.59,79.12) v2(61.59,71.12) v2(61.59,71.12) v2(61.59,70.36) v2(61.59,70.36) v2(61.72,77.72) v2(61.72,73.91) v2(61.72,73.91) v2(61.72,73.15) v2(61.72,73.15) v2(61.72,72.39) v2(61.72,72.39) v2(61.85,23.37) v2(61.85,23.37) v2(61.85,23.37) v2(61.85,21.72) v2(61.85,21.72) v2(61.85,21.72) v2(61.98,45.21) v2(61.98,45.21) v2(61.98,45.21) v2(61.98,45.21) v2(61.98,45.21) v2(61.98,45.21) v2(61.98,38.48) v2(61.98,38.48) v2(61.98,38.48) v2(61.98,38.48) v2(61.98,38.48) v2(61.98,35.56) v2(61.98,35.56) v2(61.98,35.56) v2(61.98,35.56) v2(61.98,35.56) v2(61.98,32.51) v2(61.98,32.51) v2(61.98,32.51) v2(61.98,32.51) v2(61.98,32.51) v2(61.98,9.78) v2(61.98,9.78) v2(61.98,9.78) v3(13.33,64.14) v3(13.33,64.14) v3(13.33,64.14) v3(13.33,62.61) v3(13.33,62.61) v3(13.33,62.61) v3(13.33,62.61) v3(13.33,61.09) v3(13.33,61.09) v3(14.6,85.09) v3(14.6,85.09) v3(14.6,85.09) v3(14.6,85.09) v3(14.86,64.14) v3(14.86,64.14) v3(14.86,64.14) v3(14.86,62.61) v3(14.86,61.09) v3(14.86,61.09) v3(15.88,87.63) v3(15.88,87.63) v3(15.88,86.36) v3(16.38,64.14) v3(16.38,64.14) v3(16.38,64.14) v3(16.38,62.61) v3(16.38,61.09) v3(17.02,85.09) v3(17.15,87.63) v3(17.27,15.24) v3(17.27,15.24) v3(17.27,15.24) v3(17.27,14.22) v3(17.27,14.22) v3(17.27,14.22) v3(17.27,14.22) v3(18.29,16.26) v3(18.29,15.24) v3(18.29,14.22) v3(31.62,16.38) v3(32.64,17.15) v3(32.64,17.15) v3(32.64,17.15) v3(32.64,16.38) v3(32.64,16.38) v3(32.64,16.38) v3(32.64,16.38) v3(32.64,16.38) v3(45.09,34.54) v3(45.09,34.54) v3(45.09,34.54) v3(45.09,34.54) v3(45.09,34.54) v3(45.09,33.66) v3(45.09,32.77) v3(45.09,32.77) v3(45.34,95) v3(45.34,92.96) v3(45.34,92.96) v3(45.34,92.96) v3(45.34,92.96) v3(45.34,92.96) v3(45.97,33.66) v3(45.97,32.77) v3(47.37,95) v3(47.37,93.98) v3(47.37,93.98) v3(47.37,92.96) v3(47.37,92.96) v3(54.64,72.79) v3(54.64,72.79) v3(54.64,72.79) v3(54.64,72.79) v3(54.64,72.79) v3(54.64,71.19) v3(54.64,71.19) v3(54.64,71.19) v3(54.64,71.19) v3(54.64,71.19) v3(55.44,71.19) v3(55.44,71.19) v3(55.44,71.19) v3(55.44,71.19) v3(55.44,71.19)
VBUS_TYPEC: length 35.6
  TOP w0.254: v2(44.32,96.01) 45.11,96.01 U21.24
  TOP w0.305: 47.62,98.09 R106.1 ; 47.62,98.09 U19.2 ; 47.62,98.09 47.62,97.43 U19.1 ; 51.61,98.76 51.61,99.21 51.82,99.42 U20.5 ; 51.61,98.76 U20.9 51.61,98.09 ; 51.61,98.76 U20.3 ; 51.61,98.76 U20.6 47.8,98.76 R106.1 ; U20.8 51.82,97.43 ; 51.82,97.43 51.82,98.09 ; 51.82,97.43 U20.1 ; v2(5.46,17.91) 8,17.91 ; v2(5.46,17.91) v2(5.46,18.67) ; v2(5.46,17.91) v2(4.7,17.91) v2(4.7,18.67) ; 8,17.91 8,17.15 v2(5.46,17.15) v2(4.7,17.15) ; 8,17.91 JP1.1 ; 51.82,98.09 U20.2 ; 51.82,98.09 51.61,98.09 ; v2(52.07,96.01) D6.K ; R106.1 47.45,98.76 U19.3 ; R111.1 v2(53.98,96.52) ; 51.61,98.09 U20.7 ; v2(55.24,96.52) C212.1
  BOTTOM w0.305: C211.2 v2(42.04,96.01)
  vias: v2(48.77,99.57) v2(48.77,99.57) v2(48.77,98.81) v2(48.77,98.81) v2(48.77,98.81) v2(48.77,98.04) v2(48.77,98.04) v2(48.77,98.04) v2(48.77,97.28) v2(48.77,97.28) v2(48.77,97.28) v2(48.77,97.28) v2(49.53,99.57) v2(49.53,98.81) v2(49.53,98.04) v2(49.53,97.28) v2(49.53,97.28) v2(49.53,97.28)
VDD_CONNECTOR: length 11
  TOP w0.305: JP1.3 2.79,18.08 3.05,17.4
  TOP w0.635: 3.05,17.4 3.05,13.46 3.43,13.08 v2(4.45,13.08) v2(5.33,13.08)
  BOTTOM w0.305: J3.99 4.19,12.83 v2(4.45,13.08) 4.19,13.46 4.19,13.46 J3.97
  BOTTOM w0.635: v2(5.33,13.08) v2(4.45,13.08)
VDD_EXT: length 178.8
  TOP w0.203: U1.U10 v1(32.22,47.74) ; U1.U7 v1(29.82,47.74) ; U1.K4 U1.L4 v1(27.42,52.54) ; U1.M4 v1(27.42,51.74) ; U1.R16 v1(37.82,49.34) ; U1.P4 v1(27.42,50.14) U1.R4 ; U1.U11 v1(33.82,47.74) ; U1.U15 v1(37.02,47.74) ; U1.U12 v1(34.62,47.74) ; U1.D8 v1(31.42,58.94) U1.D9 ; U1.T16 v1(37.82,48.54) ; U1.U6 v1(29.02,47.74) ; U1.U9 v1(31.42,47.74) ; U1.N16 v1(37.82,50.94) ; U1.N4 v1(27.42,50.94) ; U1.P16 v1(37.82,50.14) ; U1.U13 v1(35.42,47.74) ; U1.T5 v1(29.02,48.54) ; U1.M16 v1(37.82,51.74) ; U1.U14 v1(36.22,47.74) ; U1.U8 v1(30.62,47.74)
  TOP w0.254: v1(20.07,13.84) 20.07,14.1 19.67,14.49 U15.2 ; 29.34,17.14 C169.1 ; 29.34,17.14 29.34,16.64 ; 29.34,17.14 U5.11 ; v2(30.48,14.99) 30.99,15.11 31.38,15.11 U5.15 ; v2(34.8,16.64) U5.3 ; U5.12 29.34,16.64 ; 29.34,16.64 29.34,16.14 U5.13 ; 49.02,14.98 48.89,15.1 48.89,15.17 U14.3 ; U5.4 34.92,17.14 C170.2
  TOP w0.305: v1(33.82,43.34) C88.1 ; v2(57.91,62.36) 53.85,62.36 C150.1 ; v1(4.45,8.38) R95.1 ; 49.02,14.98 49.78,15.29 49.78,9.4 42.93,9.4 R62.2 ; U3.1 57.02,59.88 57.28,59.62 57.28,58.23 57.02,57.98 U3.3 ; C172.1 27.94,17.93 v2(27.94,16.89) ; C172.1 26.92,17.93 v2(26.92,16.89) ; C172.1 27.43,18.09 27.3,18.22 C169.1 ; TP4.1 20.7,27.3 ; TP4.1 v2(19.3,26.42) ; TP4.1 v2(19.3,28.19) ; TP4.1 v2(17.53,28.19) ; TP4.1 R53.1 ; TP4.1 v2(17.53,26.42) ; TP4.1 19.05,24.51 L4.2 ; 20.7,27.3 C165.1 C164.1 ; 20.7,27.3 C166.1 ; 45.02,42.62 v1(45.02,43.34) ; 48.26,15.17 C156.1 ; U1.D11 U1.D10 v1(32.22,58.94) ; C126.1 v1(42.02,43.34) ; 30.62,42.62 v1(30.62,43.34) ; 34.92,17.68 C171.2 37.21,17.68 v2(37.21,16.64) C217.2 ; v1(25.82,43.34) 25.82,42.62 ; v1(21.02,43.34) 21.02,42.62 ; v1(5.71,8.38) R99.1 ; v2(17.78,9.65) C163.1 ; v1(29.02,43.34) C82.1 ; v1(43.42,43.34) 43.42,42.62 ; v1(32.22,43.34) C83.1 ; v2(19.05,9.65) R55.1 ; 35.42,42.62 v1(35.42,43.34)
  L2_PWR w0.406: 17.77,27.95 17.88,27.84 ; 19.06,27.95 18.95,27.84 ; 19.06,26.66 18.95,26.77 ; 17.77,26.66 17.88,26.77
  L4_SIG w0.305: v1(5.71,8.38) 5.84,8.38
  L4_SIG w0.635: 27.42,42.8 v1(27.42,43.34) v1(25.82,43.34) v1(24.22,43.34) v1(22.62,43.34) v1(21.02,43.34)
  L4_SIG w1.016: 27.42,42.8 v1(19.81,42.8) v1(17.4,42.8) 10.03,42.8 7.37,40.13 7.37,8.38 5.84,8.38 ; v1(5.71,8.38) v1(4.45,8.38)
  BOTTOM w0.305: 27.42,42.62 v1(27.42,43.34) ; 32.22,42.62 v1(32.22,43.34) ; 43.42,42.62 v1(43.42,43.34) ; v1(27.42,50.14) 27.57,49.74 C72.1 ; C40.1 18.67,43.04 18.67,42.8 ; v1(30.62,43.34) C73.1 ; v1(37.82,50.94) C79.1 ; 47.22,43.34 C39.1 ; 47.22,43.34 v1(48.42,43.34) ; 47.22,43.34 v1(46.02,43.34) ; v1(42.02,43.34) C78.1 ; 18.67,42.8 v1(17.4,42.8) ; 18.67,42.8 v1(19.81,42.8) ; v1(21.02,43.34) C75.1 ; v1(45.02,43.34) 45.02,42.62 ; 22.62,42.62 v1(22.62,43.34) ; v1(35.42,43.34) 35.42,42.62 ; 33.82,42.62 v1(33.82,43.34) ; 25.82,42.62 v1(25.82,43.34) ; 29.02,42.62 v1(29.02,43.34) ; v1(24.22,43.34) 24.22,42.62
  vias: v2(7.87,6.99) v2(7.87,6.99) v2(7.87,6.22) v2(10.16,6.99) v2(10.16,6.99) v2(10.16,6.22) v2(10.16,6.22) v2(26.92,16.13) v2(27.94,16.13) v2(27.94,16.13) v2(29.21,16.89) v2(29.21,16.13) v2(29.21,16.13) v2(35.81,16.64) v2(35.81,16.64) v2(39.5,13.08) v2(39.5,13.08) v2(39.5,12.32) v2(39.5,12.32) v2(39.5,11.56) v2(39.5,11.56) v2(40.51,13.08) v2(40.51,12.32) v2(40.51,11.56) v2(40.51,11.56) v2(41.53,13.08) v2(41.53,12.32) v2(41.53,12.32) v2(41.53,11.56) v2(41.53,11.56) v2(57.91,63.12) v2(57.91,63.12) v2(57.91,61.59) v2(57.91,61.59) v2(58.67,63.12) v2(58.67,62.36) v2(58.67,61.59)
VDD_INPUT: length 36.8
  TOP w0.254: C160.1 14.6,16.49 U15.11 ; U15.6 20.95,16.49 C158.1
  TOP w0.305: C161.1 10.41,18.39 v2(10.41,19.43) v2(10.41,20.19) ; C161.1 12.57,18.39 ; C161.1 v2(11.56,19.43) v2(11.56,20.19) 11.56,21.36 C155.1 11.36,21.16 JP1.2 ; 12.57,18.39 C160.1 ; 12.57,18.39 v2(12.57,19.43) v2(12.57,20.19) ; 22.99,18.39 C158.1 ; 22.99,18.39 v2(22.99,19.43) ; 22.99,18.39 C159.1 ; C159.1 25.02,18.39 v2(25.02,19.43) ; C159.1 v2(24,19.43)
  BOTTOM w0.305: v2(12.57,19.43) 12.57,19.3 15.62,19.3 R29.1
VDD_INT: length 137.4
  TOP w0.203: U1.J14 v1(36.22,54.94) ; U1.H17 v1(38.62,55.74) ; v1(37.02,52.54) U1.L15 v1(36.22,52.54) U1.L14 ; U1.P9 v1(31.42,50.14) ; U1.E7 v1(29.82,58.14) ; U1.N14 v1(35.42,51.74) ; U1.R12 v1(34.62,49.34) ; U1.J17 v1(38.62,54.94) ; U1.R11 v1(33.82,49.34) ; U1.J5 v1(28.22,54.14) U1.K5 ; U1.M5 v1(28.22,51.74) ; U1.P10 v1(32.22,50.14) ; U1.J15 v1(37.02,54.94) ; v1(32.22,57.34) U1.E10 ; U1.R10 v1(32.22,49.34) ; v1(28.22,58.14) U1.E5 ; U1.R8 v1(30.62,49.34) ; U1.R9 v1(31.42,49.34) ; U1.P11 v1(33.82,50.14) ; U1.P13 v1(35.42,50.14) ; v1(36.22,51.74) U1.M14 ; U1.N6 v1(29.02,50.94) ; U1.N7 v1(29.82,50.94) ; U1.P6 v1(29.02,50.14) U1.R6 ; v1(28.22,57.34) U1.F5 ; v1(27.42,58.14) U1.E4 ; U1.K16 v1(37.82,54.14) ; U1.G4 v1(27.42,56.54) ; U1.F16 v1(37.82,57.34) U1.E17 ; v1(33.82,58.14) U1.E11 ; U1.R14 v1(36.22,49.34) ; U1.K15 v1(37.02,54.14) ; U1.R13 v1(35.42,49.34) ; v1(35.42,58.14) U1.E13 ; U1.E6 v1(29.02,58.14) ; U1.P8 v1(30.62,50.14) ; U1.E8 v1(30.62,58.14) ; v1(34.62,58.14) U1.E12 ; U1.M6 v1(29.02,51.74) ; v1(37.02,58.14) U1.E15 ; U1.P12 v1(34.62,50.14) ; v1(32.22,58.14) U1.E9 ; U1.P14 v1(36.22,50.14) ; U1.R7 v1(29.82,49.34) ; U1.F17 v1(38.62,57.34) ; U1.H5 v1(28.22,54.94) U1.H4 ; U1.J16 v1(37.82,54.94) ; U1.G16 v1(37.82,56.54) ; U1.H16 v1(37.82,55.74) ; U1.K14 v1(36.22,54.14) ; U1.E16 v1(37.82,58.14) ; v1(36.22,58.14) U1.E14 ; U1.G5 v1(28.22,56.54) ; U1.P7 v1(29.82,50.14) ; U1.G17 v1(38.62,56.54) ; U1.F4 v1(27.42,57.34) ; U1.L5 v1(28.22,52.54)
  TOP w0.305: 34.87,24.61 34.98,24.64 34.98,24.26 ; 34.87,24.61 34.54,25.68 v2(34.04,24.38) 34.87,24.61 ; 34.87,24.61 34.97,24.26 C181.1 ; v2(33.15,24.64) 33.15,23.44 L5.2 ; R98.1 v2(1.91,8.38) ; R61.2 27.3,14.99 26.92,14.6 v2(26.92,13.59) ; v2(31.12,24.64) 31.12,23.44 L5.2 ; C63.1 v1(23.02,61.34) ; v2(30.23,22.61) 29.08,22.73 C179.1 ; L5.2 v2(32.13,24.64) C180.1 C179.1 ; C179.1 29.08,24.38 v2(30.23,24.38) ; C179.1 v2(30.23,23.49) ; C70.1 v1(23.02,50.54) ; C181.1 35.18,22.61 v2(34.04,22.61) ; C181.1 v2(34.04,23.49) ; C181.1 C184.1 35.2,27.85 35.05,28 C177.1 ; C53.1 v1(23.02,54.14) ; v2(33.02,10.79) C178.1 ; R116.2 v2(35.94,9.53) 37.46,9.53 C218.2 ; v2(34.67,11.94) R64.1 ; C52.1 v1(23.02,55.34) ; C57.1 v1(23.02,58.14) ; C55.1 v1(23.02,49.14) ; v1(23.02,56.74) C62.1 ; C54.1 v1(23.02,52.94)
  BOTTOM w0.14: C152.1 29.08,26.17 29.08,26.29 28.38,26.99 28.38,27.43 28.64,27.69 31.75,27.69 32.26,28.19 32.26,35.94 33.15,36.83 33.15,43.67 33.42,43.94 U1.R11 v1(33.82,50.14)
  BOTTOM w0.305: v1(23.02,51.74) C115.1 ; v1(32.22,50.14) C123.1 ; v1(23.02,54.14) C53.1 ; C59.1 36.22,52.99 v1(36.22,52.54) ; v1(23.02,55.34) C52.1 ; v1(38.62,57.34) C60.1 ; 28.3,55.74 28.22,55.66 v1(28.22,54.94) ; v2(30.23,24.38) 29.09,24.38 C152.1 ; v1(23.02,52.94) C54.1 ; v1(23.02,49.14) C55.1 ; 15.37,56.44 v2(15.37,54.61) ; 15.37,56.44 v2(15.37,58.29) ; 15.37,56.44 L1.1 ; v1(23.02,59.74) C66.1 ; v1(37.82,54.14) 37.82,53.34 C56.1 37.74,53.34 ; v1(34.62,50.14) C130.1 ; v1(23.02,58.14) C57.1 ; v1(23.02,61.34) C63.1 ; v1(33.82,50.14) C120.1 ; v1(23.02,50.54) C70.1 ; v2(1.91,8.38) v2(1.02,8.38) v2(1.02,7.62) ; v1(30.62,50.14) C131.1 ; v1(28.22,54.14) 28.22,53.69 C61.1 ; v1(29.02,51.74) C122.1 ; R120.1 24.94,54.22 24.42,54.74 24.42,55.14 v1(24.62,55.34) ; C41.1 18.92,52.94 v1(18.92,54.23) ; v1(31.42,50.14) C121.1 ; v1(19.62,50.54) C42.1 ; v1(23.02,47.94) C67.1 ; C62.1 v1(23.02,56.74)
  vias: v2(1.02,9.91) v2(1.02,9.14) v2(1.91,7.62)
VDD_PLL: length 16.6
  TOP w0.305: U1.L6 U1.K6 v1(29.02,54.14)
  L4_SIG w0.305: v1(23.82,55.34) 25.52,53.64 28.52,53.64 v1(29.02,54.14)
  BOTTOM w0.305: R119.1 v1(23.82,55.34) 23.15,56.01 20.45,56.01 20.19,55.75 19.62,55.75 C33.1 17.72,55.69 L1.2 ; C32.1 v1(29.02,54.14)
VDD_VREF_EXT: length 105
  TOP w0.203: U1.N5 v1(28.22,50.94) ; U1.T15 v1(37.02,48.54) ; v1(35.42,48.54) U1.T13 ; v1(33.82,48.54) U1.T11 ; U1.R15 v1(37.02,49.34) ; U1.T9 v1(31.42,48.54) ; U1.T7 v1(29.82,48.54) U1.T6 ; v1(34.62,48.54) U1.T12 ; U1.P15 v1(37.02,50.14) ; U1.M15 v1(37.02,51.74) ; U1.P5 v1(28.22,50.14) U1.R5 ; U1.T10 v1(32.22,48.54) ; U1.T8 v1(30.62,48.54) ; v1(36.22,48.54) U1.T14 ; U1.N15 v1(37.02,50.94)
  TOP w0.305: 43.74,48.54 v1(43.02,48.54) ; C37.1 v1(46.22,48.54) ; 22.3,45.34 22.99,45.34 v1(22.99,45.34) ; 60.96,59.88 TP2.1 v2(60.45,57.53) ; 60.96,59.88 U3.5 ; 60.96,59.88 C154.1 ; v1(46.22,45.34) 46.94,45.34 ; U1.G11 v1(33.82,55.74) ; v1(43.02,50.14) C38.1 ; v1(22.99,46.61) C36.1 ; v1(46.22,46.94) C48.1 ; v1(3.18,8.38) R96.1 ; v1(46.22,51.74) C49.1 ; v1(46.22,50.14) C47.1 ; C46.1 v1(43.02,45.34) ; U1.G10 v1(33.02,55.74) ; R124.1 11.43,13.84 v2(10.29,13.84)
  TOP w0.508: v2(61.47,56.01) R26.1
  L4_SIG w0.508: v1(3.18,8.38) 2.16,9.4 2.16,42.55 2.79,43.18 5.83,43.18 7.35,44.7 17.06,44.7 v1(17.42,44.34)
  L7_PWR w0.406: 61.61,59.7 61.5,59.59 ; 60.31,59.7 60.42,59.59 ; 61.61,58.41 61.5,58.52 ; 60.31,58.41 60.42,58.52
  BOTTOM w0.305: v2(10.29,13.84) 10.29,11.94 8.13,9.78 3.68,9.78 3.18,9.27 v1(3.18,8.38) ; C36.1 v1(22.99,46.61) ; 50.42,48.54 v1(49.22,48.54) ; 50.42,48.54 v1(51.62,48.54) ; 50.42,48.54 C44.1 ; 18.67,45.21 v1(19.81,45.21) ; 18.67,45.21 v1(17.4,45.21) ; 18.67,45.21 C43.1 ; 46.94,51.74 v1(46.22,51.74) ; C38.1 v1(43.02,50.14) ; 46.94,45.34 v1(46.22,45.34) ; v1(43.02,48.54) 43.74,48.54 ; v1(46.22,48.54) C37.1 ; 43.74,46.94 v1(43.02,46.94) ; 46.94,50.14 v1(46.22,50.14) ; v1(22.99,45.34) 22.32,45.34 ; v1(43.02,45.34) 43.74,45.34 ; 46.94,46.94 v1(46.22,46.94)
  vias: v2(60.45,56.77) v2(60.45,56.01) v2(60.45,56.01) v2(61.47,57.53) v2(61.47,56.77) v2(61.47,56.77)
1_8V: length 36.2
  TOP w0.305: R97.1 6.99,9.14 8.64,9.14 v2(10.29,10.79) ; 57.79,55.24 FER3.1
  TOP w0.508: v2(59.69,51.43) R14.1 ; v2(61.47,50.67) v2(61.47,51.43) R26.2
  TOP w0.635: 57.79,55.24 58.93,55.24 v2(59.69,54.48)
  L4_SIG w0.305: v2(18.16,32.64) 17.02,32.64 16.64,32.26 16.64,20.7 11.56,15.62 11.56,12.06 v2(10.29,10.79)
  BOTTOM w0.305: R27.1 v2(48.89,36.83)
1_35V: length 86.3
  TOP w0.203: U13.C1 v1(28.22,72.74) ; U1.F14 v1(36.22,57.34) ; U13.N1 v1(36.22,72.74) ; U13.E9 v1(29.82,79.94) ; U13.A1 v1(26.62,72.74) ; U1.F15 v1(37.02,57.34) ; U13.D9 v1(29.02,79.94) ; U1.F8 v1(30.62,57.34) ; U1.F12 v1(34.62,57.34) ; U13.K2 v1(33.82,73.54) ; U13.F1 v1(30.62,72.74) ; U13.H9 v1(32.22,79.94) ; U13.K8 v1(33.82,79.14) ; U13.B2 v1(27.42,73.54) ; U13.N9 v1(36.22,79.94) ; U1.G15 v1(37.02,56.54) ; U1.J6 v1(29.02,54.94) ; U13.G7 v1(31.42,78.34) ; U1.F11 v1(33.82,57.34) ; U1.G9 v1(31.42,56.54) ; U1.G8 v1(30.62,56.54) ; U13.H2 v1(32.22,73.54) ; U1.F13 v1(35.42,57.34) ; U13.C9 v1(28.22,79.94) ; v1(29.82,56.54) U1.G7 ; U13.R1 v1(37.82,72.74) ; v1(29.82,57.34) U1.F7 ; U13.D2 v1(29.02,73.54) ; U13.A8 v1(26.62,79.14) ; U1.F6 v1(29.02,57.34) ; U1.H6 v1(29.02,55.74) ; U1.G12 v1(34.62,56.54) ; U1.G14 v1(36.22,56.54) ; U13.R9 v1(37.82,79.94) ; U1.H14 v1(36.22,55.74) ; U1.G6 v1(29.02,56.54) ; U1.F10 v1(32.22,56.54) ; v1(37.02,55.74) U1.H15 ; U1.F9 v1(31.42,57.34) ; U1.G13 v1(35.42,56.54)
  TOP w0.254: v2(57.66,71.12) 57.66,71.49 57.3,71.49 U12.2
  TOP w0.305: v1(43.75,58.93) 43.75,59.72 C94.1 ; v1(43.02,62.94) C96.1 ; v1(29.82,54.94) U1.J7 U1.K7 ; C101.1 v1(33.82,63.14) ; L3.2 48.66,21.21 C216.1 C215.1 ; v1(43.02,61.34) C93.1 ; v1(32.22,63.14) C98.1 ; v1(29.82,55.74) U1.H7 ; C215.1 v2(45.72,22.86) ; C215.1 C214.1 ; v1(43.02,58.14) C104.1 ; v1(38.62,63.14) C106.1 ; R63.1 45.44,11.58 C151.1 v2(45.47,10.79) ; v1(37.02,63.14) C105.1 ; v1(35.42,63.14) C103.1 ; C100.1 v1(46.22,62.94) ; v1(46.22,61.34) C108.1
  TOP w0.406: v2(57.66,70.36) 58.74,70.36 ; 58.74,70.36 C6.1 ; 58.74,70.36 58.74,71.12 v2(57.66,71.12) ; v1(28.22,72.74) 28.22,71.22 ; v2(57.66,68.07) 58.74,68.07 C5.1 58.74,67.31 v2(57.66,67.31) ; v1(39.22,69.54) R6.1 ; v1(37.82,79.94) 37.82,81.46 ; C11.1 v1(32.22,69.54) ; v1(32.22,79.94) 32.22,81.46 ; v1(28.22,79.94) 28.22,81.46 ; v1(29.82,79.94) 29.82,81.46 ; v1(37.82,72.74) 37.82,71.22 ; R3.1 v1(36.22,83.14) ; v1(30.62,72.74) 30.62,71.22
  TOP w0.508: R100.1 57.63,68.1 v2(57.66,68.07)
  L7_PWR w0.406: 45.73,25.39 45.62,25.5 ; 44.44,25.39 44.55,25.5 ; 45.73,26.68 45.62,26.57 ; 44.44,26.68 44.55,26.57
  BOTTOM w0.305: v1(43.18,64.01) C90.1 ; v1(23.02,62.94) 22.35,63.61 21.78,63.61 21.76,63.63 ; v1(33.82,63.14) C101.1 ; v1(35.42,63.14) C103.1 ; v1(43.02,62.94) C118.1 ; v1(46.22,61.34) C108.1 ; v1(35.42,56.54) C91.1 ; C104.1 v1(43.02,58.14) ; v1(5.33,14.1) 5.33,15.11 5.59,15.37 J3.92 ; 21.76,63.63 C111.1 ; 21.76,63.63 21.31,63.63 v1(20.62,62.94) ; v1(34.62,56.54) C97.1 ; v1(46.22,62.94) C100.1 ; C98.1 v1(32.22,63.14) ; v1(37.02,63.14) C119.1 ; v1(38.62,63.14) C106.1 ; v1(43.75,58.93) 43.75,59.74 C94.1 ; v1(30.62,56.54) C92.1 ; C117.1 v1(43.02,61.34)
  vias: v2(43.18,24.38) v2(43.18,24.38) v2(43.18,23.62) v2(43.18,23.62) v2(43.18,22.86) v2(43.18,22.86) v2(44.45,24.38) v2(44.45,23.62) v2(44.45,22.86) v2(44.45,22.86) v2(45.72,24.38) v2(45.72,23.62) v2(45.72,23.62) v2(46.99,24.38) v2(46.99,23.62) v2(46.99,23.62) v2(46.99,22.86) v2(46.99,22.86) v2(57.66,69.6) v2(57.66,69.6) v2(57.66,68.83)
AUDIO_CLK: length 57.7
  TOP w0.14: R24.2 50.04,33.02 50.04,34.16 49.66,34.54 49.66,37.08 49.28,37.46 48.51,37.46 v2(47.88,38.1) ; v1(5.46,31.88) 5.84,31.88 6.22,32.26 6.22,38.1 6.73,38.61 v1(9.27,38.61)
  L4_SIG w0.14: v2(47.88,38.1) 37.72,38.1 37.46,38.35 30.48,38.35 29.97,38.86 17.4,38.86 16.38,37.85 15.49,37.85 14.48,38.86 10.79,38.86 10.54,38.61 v1(9.27,38.61)
  BOTTOM w0.14: J3.40 v1(5.46,31.88)
CC1: length 24.6
  TOP w0.254: U21.2 43.94,94.73 v2(43.56,95) 43.94,95.23 U21.1
  TOP w0.305: v2(29.46,91.44) D3.2 31.23,91.44 31.48,91.69 P3.A5
  L4_SIG w0.305: v2(43.56,95) 44.32,94.23 44.32,92.33 43.43,91.44 v2(29.46,91.44)
CC2: length 21.7
  TOP w0.254: U21.5 43.94,93.23 v2(43.56,93.47) 43.94,93.73 U21.4
  TOP w0.305: 30.48,92.09 30.48,94.49 30.23,94.74 29.86,94.74 29.73,94.87 P3.B5 ; 30.48,92.09 D3.1 ; 30.48,92.09 29.97,92.09 v2(29.46,92.33)
  L4_SIG w0.305: v2(29.46,92.33) 30.61,92.33 30.86,92.08 42.16,92.08 v2(43.56,93.47)
CLK1: length 55.3
  TOP w0.14: R30.2 v2(46.99,39.37) ; v1(5.46,31.24) 4.95,31.24 4.57,31.62 4.57,39.12 5.08,39.62 v1(9.27,39.62)
  L4_SIG w0.14: v1(9.27,39.62) 10.41,39.62 11.43,40.64 13.84,40.64 14.99,39.5 16.89,39.5 17.55,40.16 20.6,40.16 21.42,39.34 30.4,39.34 30.8,38.94 40.26,38.94 40.46,38.74 46.36,38.74 v2(46.99,39.37)
  BOTTOM w0.14: J3.42 v1(5.46,31.24)
CLK2: length 46.8
  TOP w0.14: v1(8.51,30.99) 9.14,31.62 9.14,33.68 8.54,34.29 8.54,34.8 9.27,35.53 v1(9.27,35.56)
  L4_SIG w0.14: v2(44.32,30.48) 43.56,31.24 42.67,31.24 41.91,30.48 30.86,30.48 29.34,32 21.59,32 18.67,34.92 17.02,34.92 16.51,34.42 10.92,34.42 9.78,35.56 v1(9.27,35.56)
  BOTTOM w0.14: v2(44.32,30.48) 44.32,31.75 R31.2 ; J3.44 8.13,30.61 v1(8.51,30.99)
DAI0_PIN01: length 58.5
  TOP w0.203: v1(30.62,45.34) U1.Y8
  L4_SIG w0.14: v1(61.85,13.21) 60.2,13.21 59.69,12.7 54.61,12.7 54.1,13.21 v2(53.34,13.21)
  L5_SIG w0.14: v1(32.89,33.78) 32.13,34.54 32.13,39.66 31.02,40.77 31.02,43.94 30.62,44.34 v1(30.62,45.34)
  BOTTOM w0.14: v1(32.89,33.78) 34.67,33.78 41.15,27.3 49.4,27.3 50.16,26.54 50.16,21.34 51.18,20.32 51.18,15.37 v2(53.34,13.21) ; J1.3 61.34,13.46 v1(61.85,13.21)
DAI0_PIN02: length 55.1
  TOP w0.203: v1(31.42,46.94) U1.V9
  L4_SIG w0.14: v1(58.93,14.48) 58.42,14.99 54.61,14.99 54.1,15.49 v2(53.34,15.49)
  L5_SIG w0.14: v1(31.42,46.94) 31.82,46.54 32.69,46.54 32.89,46.34 v1(32.89,35.34)
  BOTTOM w0.14: v1(32.89,35.34) 34.42,35.34 40.9,28.96 49.53,28.96 51.18,27.3 51.18,21.84 52.2,20.83 52.2,16.64 v2(53.34,15.49) ; v1(58.93,14.48) 59.31,14.1 J1.5
DAI0_PIN03: length 58.1
  TOP w0.203: v1(31.42,46.14) U1.W9
  L4_SIG w0.14: v2(53.34,14.35) 53.98,14.35 54.61,13.72 61.09,13.72 v1(61.85,14.48)
  L5_SIG w0.14: v1(31.42,46.14) 31.82,45.74 31.82,40.63 32.38,40.07 32.38,35.05 v1(32.89,34.54)
  BOTTOM w0.14: v2(53.34,14.35) 51.69,16 51.69,20.57 50.67,21.59 50.67,26.92 49.91,27.69 41.4,27.69 34.54,34.54 v1(32.89,34.54) ; J1.7 61.34,14.73 v1(61.85,14.48)
DAI0_PIN04: length 52.9
  TOP w0.203: v1(31.42,45.34) U1.Y9
  L4_SIG w0.14: v1(58.93,15.75) 58.42,15.24 57.15,15.24 55.63,16.76 55.63,30.23 52.58,33.27 52.58,35.56 48.2,39.94 37.02,39.94 35.62,41.34 35.02,41.34 34.62,41.74 32.62,41.74 31.42,42.94 v1(31.42,45.34)
  BOTTOM w0.14: J1.9 59.31,15.37 v1(58.93,15.75)
DAI0_PIN05: length 56.2
  TOP w0.203: v1(32.22,46.14) U1.W10
  L4_SIG w0.14: v1(61.85,15.75) 60.45,15.75 59.94,16.26 56.77,16.26 56.01,17.02 56.01,30.48 53.09,33.4 53.09,35.81 48.66,40.24 37.12,40.24 35.62,41.74 35.22,41.74 34.82,42.14 32.62,42.14 31.82,42.94 31.82,45.74 v1(32.22,46.14)
  BOTTOM w0.14: J1.11 61.34,16 v1(61.85,15.75)
DAI0_PIN06: length 53.5
  TOP w0.203: v1(32.22,46.94) U1.V10
  L4_SIG w0.14: v1(32.22,46.94) 33.02,46.14 33.02,43.54 33.62,42.94 34.82,42.94 35.22,42.54 37.22,42.54 38.36,41.4 48.82,41.4 50.09,40.13 53.21,40.13 54.1,39.24 54.1,33.71 56.82,30.99 56.82,18.11 57.28,17.65 58.29,17.65 v1(58.93,17.02)
  BOTTOM w0.14: v1(58.93,17.02) 59.31,16.64 J1.13
DAI0_PIN07: length 54.2
  TOP w0.203: v1(32.22,45.34) U1.Y10
  L4_SIG w0.14: v1(32.22,45.34) 32.62,44.94 32.62,43.54 33.62,42.54 34.82,42.54 35.22,42.14 36.62,42.14 38.22,40.54 49.12,40.54 53.63,36.04 53.63,33.53 56.42,30.73 56.42,17.15 57.06,16.51 61.34,16.51 v1(61.85,17.02)
  BOTTOM w0.14: v1(61.85,17.02) 61.34,17.27 J1.15
DAI0_PIN08: length 50.4
  TOP w0.203: v1(33.82,46.14) U1.W11
  L4_SIG w0.14: v1(58.93,18.29) 58.42,18.8 57.6,18.8 57.22,19.18 57.22,31.24 54.61,33.85 54.61,39.37 53.47,40.51 50.19,40.51 48.97,41.74 38.42,41.74 37.22,42.94 35.22,42.94 33.42,44.74 33.42,45.74 v1(33.82,46.14)
  BOTTOM w0.14: v1(58.93,18.29) 59.31,17.91 J1.17
DAI0_PIN09: length 54.1
  TOP w0.203: v1(33.82,46.94) U1.V11
  L4_SIG w0.14: v1(58.55,39.62) 55.88,39.62 54.24,41.26 50.66,41.26 49.28,42.65 38.81,42.65 37.06,44.4 35,44.4 34.21,45.19 34.21,46.55 v1(33.82,46.94)
  L5_SIG w0.14: v1(61.85,18.8) 60.96,19.69 60.96,39.12 60.45,39.62 v1(58.55,39.62)
  BOTTOM w0.14: J1.19 61.34,18.54 v1(61.85,18.8)
